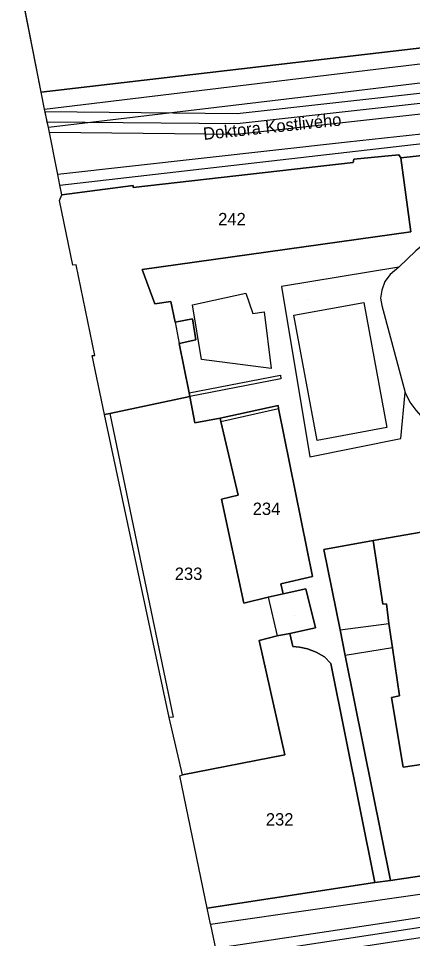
# Model space of a CAD drawing. Extents: x -263423 to -261326, y -1240067 to -1237864.
# Drawn here: x -263383 to -263319.3, y -1239723.2 to -1239574.4 of the extents above; entities that cross this region are included whole.
import ezdxf

# ---------------------------------------------------------------- set-up
doc = ezdxf.new("R2010")
doc.units = 0
for name, color, linetype in [('body_kn', 7, 'Continuous'), ('katuz_linie', 7, 'Continuous'), ('kladpar_druhypozemkov', 7, 'Continuous'), ('kladpar_hranice', 7, 'Continuous'), ('kladpar_parcelnecisla', 7, 'Continuous'), ('kladpar_plochy', 7, 'Continuous'), ('linie', 7, 'Continuous'), ('popisy', 7, 'Continuous'), ('tarchy_linie', 7, 'Continuous'), ('zappar_hrandruhpozemk', 7, 'Continuous'), ('zuob_linie', 7, 'Continuous'), ('zuob_plochy', 7, 'Continuous')]:
    doc.layers.add(name, color=color, linetype=linetype)

msp = doc.modelspace()

# ---------------------------------------------------------------- linework, layer by layer
at = {"layer": 'body_kn'}
for p, q in [((-263328.37, -1239583), (-263328.37, -1239583)), ((-263379.33, -1239586.34), (-263379.33, -1239586.34)), ((-263328.37, -1239586.11), (-263328.37, -1239586.11)), ((-263378.78, -1239589.07), (-263378.78, -1239589.07)), ((-263378.78, -1239589.07), (-263378.78, -1239589.07)), ((-263378.7, -1239589.47), (-263378.7, -1239589.47)), ((-263347.65, -1239589.78), (-263347.65, -1239589.78)), ((-263378.35, -1239591.18), (-263378.35, -1239591.18)), ((-263378.18, -1239592.03), (-263378.18, -1239592.03)), ((-263378.01, -1239592.88), (-263378.01, -1239592.88)), ((-263347.67, -1239591.48), (-263347.67, -1239591.48)), ((-263347.69, -1239593.18), (-263347.69, -1239593.18)), ((-263329.82, -1239594.43), (-263329.82, -1239594.43)), ((-263328.8, -1239597.16), (-263328.8, -1239597.16)), ((-263321.5, -1239596.46), (-263321.5, -1239596.46)), ((-263321.19, -1239596.97), (-263321.19, -1239596.97)), ((-263328.93, -1239597.73), (-263328.93, -1239597.73)), ((-263328.93, -1239597.73), (-263328.93, -1239597.73)), ((-263376.65, -1239599.64), (-263376.65, -1239599.64)), ((-263376.64, -1239599.67), (-263376.64, -1239599.67)), ((-263376.3, -1239601.35), (-263376.3, -1239601.35)), ((-263376.3, -1239601.35), (-263376.3, -1239601.35)), ((-263364.49, -1239601.44), (-263364.49, -1239601.44)), ((-263364.46, -1239601.76), (-263364.46, -1239601.76)), ((-263375.99, -1239602.91), (-263375.99, -1239602.91)), ((-263376.39, -1239603.84), (-263376.39, -1239603.84)), ((-263319.59, -1239608.9), (-263319.59, -1239608.9)), ((-263374.23, -1239614.31), (-263374.23, -1239614.31)), ((-263373.67, -1239614.26), (-263373.67, -1239614.26)), ((-263363.01, -1239615.03), (-263363.01, -1239615.03)), ((-263321.55, -1239614.62), (-263321.55, -1239614.62)), ((-263321.55, -1239614.62), (-263321.55, -1239614.62)), ((-263322.95, -1239615.83), (-263322.95, -1239615.83)), ((-263340.47, -1239617.74), (-263340.47, -1239617.74)), ((-263323.77, -1239616.97), (-263323.77, -1239616.97)), ((-263346.24, -1239618.83), (-263346.24, -1239618.83)), ((-263324.47, -1239619.64), (-263324.47, -1239619.64)), ((-263324.28, -1239618.37), (-263324.28, -1239618.37)), ((-263360.97, -1239620.55), (-263360.97, -1239620.55)), ((-263358.37, -1239620.17), (-263358.37, -1239620.17)), ((-263354.88, -1239620.74), (-263354.88, -1239620.74)), ((-263354.88, -1239620.74), (-263354.88, -1239620.74)), ((-263327.2, -1239620.34), (-263327.2, -1239620.34)), ((-263327.2, -1239620.34), (-263327.2, -1239620.34)), ((-263324.28, -1239620.84), (-263324.28, -1239620.84)), ((-263345.1, -1239622.13), (-263345.1, -1239622.13)), ((-263343.32, -1239621.87), (-263343.32, -1239621.87)), ((-263338.49, -1239622.38), (-263338.49, -1239622.38)), ((-263357.67, -1239623.53), (-263357.67, -1239623.53)), ((-263357.67, -1239623.53), (-263357.67, -1239623.53)), ((-263354.87, -1239622.96), (-263354.87, -1239622.96)), ((-263357.03, -1239626.96), (-263357.03, -1239626.96)), ((-263354.36, -1239626.39), (-263354.36, -1239626.39)), ((-263371.08, -1239628.9), (-263371.08, -1239628.9)), ((-263370.65, -1239628.9), (-263370.65, -1239628.9)), ((-263353.41, -1239629.56), (-263353.41, -1239629.56)), ((-263342.17, -1239631.02), (-263342.17, -1239631.02)), ((-263340.64, -1239632.1), (-263340.64, -1239632.1)), ((-263340.58, -1239632.67), (-263340.58, -1239632.67)), ((-263355.43, -1239634.96), (-263355.43, -1239634.96)), ((-263355.43, -1239634.96), (-263355.43, -1239634.96)), ((-263355.31, -1239635.54), (-263355.31, -1239635.54)), ((-263320.52, -1239634.88), (-263320.52, -1239634.88)), ((-263320.52, -1239634.88), (-263320.52, -1239634.88)), ((-263341.02, -1239636.99), (-263341.02, -1239636.99)), ((-263340.96, -1239637.5), (-263340.96, -1239637.5)), ((-263319.75, -1239636.47), (-263319.75, -1239636.47)), ((-263369.09, -1239638.47), (-263369.09, -1239638.47)), ((-263368.23, -1239638.29), (-263368.23, -1239638.29)), ((-263368.23, -1239638.29), (-263368.23, -1239638.29)), ((-263350.42, -1239639.03), (-263350.42, -1239639.03)), ((-263350.42, -1239639.03), (-263350.42, -1239639.03)), ((-263354.48, -1239639.79), (-263354.48, -1239639.79)), ((-263350.29, -1239639.6), (-263350.29, -1239639.6)), ((-263350.29, -1239639.6), (-263350.29, -1239639.6)), ((-263323.49, -1239640.53), (-263323.49, -1239640.53)), ((-263334.73, -1239642.64), (-263334.73, -1239642.64)), ((-263321.21, -1239642.31), (-263321.21, -1239642.31)), ((-263335.93, -1239645.3), (-263335.93, -1239645.3)), ((-263350.21, -1239652.11), (-263350.21, -1239652.11)), ((-263347.48, -1239651.47), (-263347.48, -1239651.47)), ((-263363.86, -1239659.23), (-263363.86, -1239659.23)), ((-263325.7, -1239658.83), (-263325.7, -1239658.83)), ((-263333.63, -1239660.29), (-263333.63, -1239660.29)), ((-263335.47, -1239664.62), (-263335.47, -1239664.62)), ((-263335.47, -1239664.62), (-263335.47, -1239664.62)), ((-263340.61, -1239665.83), (-263340.61, -1239665.83)), ((-263336.55, -1239666.65), (-263336.55, -1239666.65)), ((-263342.64, -1239667.99), (-263342.64, -1239667.99)), ((-263342.64, -1239667.99), (-263342.64, -1239667.99)), ((-263340.23, -1239667.41), (-263340.23, -1239667.41)), ((-263346.58, -1239668.94), (-263346.58, -1239668.94)), ((-263324.1, -1239669.12), (-263324.1, -1239669.12)), ((-263323.53, -1239669.05), (-263323.53, -1239669.05)), ((-263335.02, -1239672.94), (-263335.02, -1239672.94)), ((-263331.02, -1239673.25), (-263331.02, -1239673.25)), ((-263331.02, -1239673.25), (-263331.02, -1239673.25)), ((-263323.15, -1239672.23), (-263323.15, -1239672.23)), ((-263341.18, -1239674.21), (-263341.18, -1239674.21)), ((-263339.15, -1239673.83), (-263339.15, -1239673.83)), ((-263344.1, -1239674.98), (-263344.1, -1239674.98)), ((-263338.64, -1239675.93), (-263338.64, -1239675.93)), ((-263337.56, -1239676.05), (-263337.56, -1239676.05)), ((-263322.57, -1239676.17), (-263322.57, -1239676.17)), ((-263322.57, -1239676.17), (-263322.57, -1239676.17)), ((-263336.29, -1239676.31), (-263336.29, -1239676.31)), ((-263334.89, -1239676.88), (-263334.89, -1239676.88)), ((-263333.55, -1239677.64), (-263333.55, -1239677.64)), ((-263330.19, -1239677.38), (-263330.19, -1239677.38)), ((-263332.54, -1239678.72), (-263332.54, -1239678.72)), ((-263322.69, -1239684.17), (-263322.69, -1239684.17)), ((-263321.42, -1239683.92), (-263321.42, -1239683.92)), ((-263358.66, -1239687.42), (-263358.66, -1239687.42)), ((-263358.03, -1239687.36), (-263358.03, -1239687.36)), ((-263339.95, -1239693.46), (-263339.95, -1239693.46)), ((-263339.95, -1239693.46), (-263339.95, -1239693.46)), ((-263320.84, -1239695.48), (-263320.84, -1239695.48)), ((-263356.95, -1239696.85), (-263356.95, -1239696.85)), ((-263356.52, -1239696.68), (-263356.52, -1239696.68)), ((-263325.39, -1239714.1), (-263325.39, -1239714.1)), ((-263322.85, -1239713.78), (-263322.85, -1239713.78)), ((-263352.5, -1239718.27), (-263352.5, -1239718.27)), ((-263351.96, -1239720.82), (-263351.96, -1239720.82)), ((-263351.96, -1239720.82), (-263351.96, -1239720.82)), ((-263322.47, -1239720.38), (-263322.47, -1239720.38)), ((-263351.94, -1239720.93), (-263351.94, -1239720.93)), ((-263322.22, -1239722), (-263322.22, -1239722))]:
    msp.add_line(p, q, dxfattribs=at)
at = {"layer": 'katuz_linie'}
msp.add_lwpolyline([(-263349.43, -1239732.71), (-263351.94, -1239720.93), (-263351.96, -1239720.82), (-263352.5, -1239718.27), (-263356.95, -1239696.85), (-263356.52, -1239696.68), (-263358.66, -1239687.42), (-263369.09, -1239638.47), (-263371.08, -1239628.9), (-263370.65, -1239628.9), (-263373.67, -1239614.26), (-263374.23, -1239614.31), (-263376.39, -1239603.84), (-263375.99, -1239602.91), (-263376.3, -1239601.35), (-263376.64, -1239599.67), (-263376.65, -1239599.64), (-263378.18, -1239592.03), (-263378.78, -1239589.07), (-263379.33, -1239586.34), (-263383.02, -1239567.53)], dxfattribs=at)
at = {"layer": 'kladpar_druhypozemkov'}
for p, q in [((-263348.1, -1239605.45), (-263348.1, -1239605.45)), ((-263336.1, -1239619.91), (-263336.1, -1239619.91)), ((-263342.7, -1239652.51), (-263342.7, -1239652.51)), ((-263355.05, -1239662.59), (-263355.05, -1239662.59)), ((-263338.4, -1239671.01), (-263338.4, -1239671.01)), ((-263340.7, -1239702.21), (-263340.7, -1239702.21))]:
    msp.add_line(p, q, dxfattribs=at)
at = {"layer": 'kladpar_hranice'}
for points in [[(-263287.38, -1239574.28), (-263287.88, -1239575.74), (-263299.62, -1239577.08), (-263300.26, -1239577.14), (-263379.33, -1239586.34), (-263383.02, -1239567.53)], [(-263309.83, -1239595.69), (-263321.19, -1239596.97), (-263321.5, -1239596.46), (-263328.8, -1239597.16), (-263328.93, -1239597.73), (-263364.46, -1239601.76), (-263364.49, -1239601.44), (-263375.99, -1239602.91), (-263376.3, -1239601.35), (-263376.64, -1239599.67), (-263376.65, -1239599.64), (-263378.18, -1239592.03), (-263378.78, -1239589.07), (-263379.33, -1239586.34), (-263300.26, -1239577.14)], [(-263317.89, -1239657.49), (-263325.7, -1239658.83), (-263333.63, -1239660.29), (-263331.02, -1239673.25), (-263330.19, -1239677.38), (-263322.85, -1239713.78), (-263325.39, -1239714.1), (-263332.54, -1239678.72), (-263333.55, -1239677.64), (-263334.89, -1239676.88), (-263336.29, -1239676.31), (-263337.56, -1239676.05), (-263338.64, -1239675.93), (-263339.15, -1239673.83), (-263335.02, -1239672.94), (-263336.55, -1239666.65), (-263340.23, -1239667.41), (-263340.61, -1239665.83), (-263335.47, -1239664.62), (-263340.96, -1239637.5), (-263341.02, -1239636.99), (-263350.42, -1239639.03), (-263354.48, -1239639.79), (-263355.31, -1239635.54), (-263355.43, -1239634.96), (-263357.03, -1239626.96), (-263354.36, -1239626.39), (-263354.87, -1239622.96), (-263357.67, -1239623.53), (-263358.37, -1239620.17), (-263360.97, -1239620.55), (-263363.01, -1239615.03), (-263319.59, -1239608.9), (-263321.19, -1239596.97), (-263309.83, -1239595.69)], [(-263328.93, -1239597.73), (-263328.8, -1239597.16), (-263321.5, -1239596.46), (-263321.19, -1239596.97), (-263319.59, -1239608.9), (-263363.01, -1239615.03), (-263360.97, -1239620.55), (-263358.37, -1239620.17), (-263357.67, -1239623.53), (-263354.87, -1239622.96), (-263354.36, -1239626.39), (-263357.03, -1239626.96), (-263355.43, -1239634.96), (-263355.31, -1239635.54), (-263368.23, -1239638.29), (-263369.09, -1239638.47), (-263371.08, -1239628.9), (-263370.65, -1239628.9), (-263373.67, -1239614.26), (-263374.23, -1239614.31), (-263376.39, -1239603.84), (-263375.99, -1239602.91), (-263364.49, -1239601.44), (-263364.46, -1239601.76), (-263328.93, -1239597.73)], [(-263350.42, -1239639.03), (-263350.29, -1239639.6), (-263347.48, -1239651.47), (-263350.21, -1239652.11), (-263346.58, -1239668.94), (-263342.64, -1239667.99), (-263340.23, -1239667.41), (-263336.55, -1239666.65), (-263335.02, -1239672.94), (-263339.15, -1239673.83), (-263341.18, -1239674.21), (-263344.1, -1239674.98), (-263339.95, -1239693.46), (-263356.52, -1239696.68), (-263358.66, -1239687.42), (-263369.09, -1239638.47), (-263368.23, -1239638.29), (-263355.31, -1239635.54), (-263354.48, -1239639.79), (-263350.42, -1239639.03)], [(-263335.47, -1239664.62), (-263340.61, -1239665.83), (-263340.23, -1239667.41), (-263342.64, -1239667.99), (-263346.58, -1239668.94), (-263350.21, -1239652.11), (-263347.48, -1239651.47), (-263350.29, -1239639.6), (-263350.42, -1239639.03), (-263341.02, -1239636.99), (-263340.96, -1239637.5), (-263335.47, -1239664.62)], [(-263312.4, -1239694.21), (-263320.84, -1239695.48), (-263322.69, -1239684.17), (-263321.42, -1239683.92), (-263322.57, -1239676.17), (-263323.15, -1239672.23), (-263323.53, -1239669.05), (-263324.1, -1239669.12), (-263325.7, -1239658.83), (-263317.89, -1239657.49)], [(-263310.98, -1239712), (-263322.85, -1239713.78), (-263330.19, -1239677.38), (-263331.02, -1239673.25), (-263333.63, -1239660.29), (-263325.7, -1239658.83), (-263324.1, -1239669.12), (-263323.53, -1239669.05), (-263323.15, -1239672.23), (-263322.57, -1239676.17), (-263321.42, -1239683.92), (-263322.69, -1239684.17), (-263320.84, -1239695.48), (-263312.4, -1239694.21)], [(-263339.95, -1239693.46), (-263344.1, -1239674.98), (-263341.18, -1239674.21), (-263339.15, -1239673.83), (-263338.64, -1239675.93), (-263337.56, -1239676.05), (-263336.29, -1239676.31), (-263334.89, -1239676.88), (-263333.55, -1239677.64), (-263332.54, -1239678.72), (-263325.39, -1239714.1), (-263352.5, -1239718.27), (-263356.95, -1239696.85), (-263356.52, -1239696.68), (-263339.95, -1239693.46)], [(-263349.43, -1239732.71), (-263351.94, -1239720.93), (-263351.96, -1239720.82), (-263352.5, -1239718.27), (-263325.39, -1239714.1), (-263322.85, -1239713.78), (-263310.98, -1239712), (-263266.99, -1239705.68)]]:
    msp.add_lwpolyline(points, dxfattribs=at)
at = {"layer": 'kladpar_plochy'}
for p, q in [((-263379.33, -1239586.34), (-263383.02, -1239567.53)), ((-263300.26, -1239577.14), (-263379.33, -1239586.34)), ((-263321.19, -1239596.97), (-263309.83, -1239595.69)), ((-263319.59, -1239608.9), (-263321.19, -1239596.97)), ((-263363.01, -1239615.03), (-263319.59, -1239608.9)), ((-263360.97, -1239620.55), (-263363.01, -1239615.03)), ((-263358.37, -1239620.17), (-263360.97, -1239620.55)), ((-263357.67, -1239623.53), (-263358.37, -1239620.17)), ((-263354.87, -1239622.96), (-263357.67, -1239623.53)), ((-263354.36, -1239626.39), (-263354.87, -1239622.96)), ((-263357.03, -1239626.96), (-263354.36, -1239626.39)), ((-263355.43, -1239634.96), (-263357.03, -1239626.96)), ((-263355.31, -1239635.54), (-263355.43, -1239634.96)), ((-263354.48, -1239639.79), (-263355.31, -1239635.54)), ((-263341.02, -1239636.99), (-263350.42, -1239639.03)), ((-263340.96, -1239637.5), (-263341.02, -1239636.99)), ((-263335.47, -1239664.62), (-263340.96, -1239637.5)), ((-263350.42, -1239639.03), (-263354.48, -1239639.79)), ((-263317.89, -1239657.49), (-263325.7, -1239658.83)), ((-263325.7, -1239658.83), (-263333.63, -1239660.29)), ((-263333.63, -1239660.29), (-263331.02, -1239673.25)), ((-263340.61, -1239665.83), (-263335.47, -1239664.62)), ((-263340.23, -1239667.41), (-263340.61, -1239665.83)), ((-263336.55, -1239666.65), (-263340.23, -1239667.41)), ((-263335.02, -1239672.94), (-263336.55, -1239666.65)), ((-263339.15, -1239673.83), (-263335.02, -1239672.94)), ((-263331.02, -1239673.25), (-263330.19, -1239677.38)), ((-263338.64, -1239675.93), (-263339.15, -1239673.83)), ((-263337.56, -1239676.05), (-263338.64, -1239675.93)), ((-263336.29, -1239676.31), (-263337.56, -1239676.05)), ((-263334.89, -1239676.88), (-263336.29, -1239676.31)), ((-263333.55, -1239677.64), (-263334.89, -1239676.88)), ((-263332.54, -1239678.72), (-263333.55, -1239677.64)), ((-263330.19, -1239677.38), (-263322.85, -1239713.78)), ((-263325.39, -1239714.1), (-263332.54, -1239678.72)), ((-263322.85, -1239713.78), (-263325.39, -1239714.1))]:
    msp.add_line(p, q, dxfattribs=at)
for points in [[(-263309.83, -1239595.69), (-263321.19, -1239596.97), (-263321.5, -1239596.46), (-263328.8, -1239597.16), (-263328.93, -1239597.73), (-263364.46, -1239601.76), (-263364.49, -1239601.44), (-263375.99, -1239602.91), (-263376.3, -1239601.35), (-263376.64, -1239599.67), (-263376.65, -1239599.64), (-263378.18, -1239592.03), (-263378.78, -1239589.07), (-263379.33, -1239586.34), (-263300.26, -1239577.14)], [(-263312.4, -1239694.21), (-263320.84, -1239695.48), (-263322.69, -1239684.17), (-263321.42, -1239683.92), (-263322.57, -1239676.17), (-263323.15, -1239672.23), (-263323.53, -1239669.05), (-263324.1, -1239669.12), (-263325.7, -1239658.83), (-263317.89, -1239657.49)], [(-263310.98, -1239712), (-263322.85, -1239713.78), (-263330.19, -1239677.38), (-263331.02, -1239673.25), (-263333.63, -1239660.29), (-263325.7, -1239658.83), (-263324.1, -1239669.12), (-263323.53, -1239669.05), (-263323.15, -1239672.23), (-263322.57, -1239676.17), (-263321.42, -1239683.92), (-263322.69, -1239684.17), (-263320.84, -1239695.48), (-263312.4, -1239694.21)], [(-263349.43, -1239732.71), (-263351.94, -1239720.93), (-263351.96, -1239720.82), (-263352.5, -1239718.27), (-263325.39, -1239714.1), (-263322.85, -1239713.78), (-263310.98, -1239712), (-263266.99, -1239705.68), (-263251.05, -1239703.32), (-263242.87, -1239702.17), (-263223.13, -1239699.36)]]:
    msp.add_lwpolyline(points, dxfattribs=at)
for points in [[(-263328.93, -1239597.73), (-263328.8, -1239597.16), (-263321.5, -1239596.46), (-263321.19, -1239596.97), (-263319.59, -1239608.9), (-263363.01, -1239615.03), (-263360.97, -1239620.55), (-263358.37, -1239620.17), (-263357.67, -1239623.53), (-263354.87, -1239622.96), (-263354.36, -1239626.39), (-263357.03, -1239626.96), (-263355.43, -1239634.96), (-263355.31, -1239635.54), (-263368.23, -1239638.29), (-263369.09, -1239638.47), (-263371.08, -1239628.9), (-263370.65, -1239628.9), (-263373.67, -1239614.26), (-263374.23, -1239614.31), (-263376.39, -1239603.84), (-263375.99, -1239602.91), (-263364.49, -1239601.44), (-263364.46, -1239601.76)], [(-263350.42, -1239639.03), (-263350.29, -1239639.6), (-263347.48, -1239651.47), (-263350.21, -1239652.11), (-263346.58, -1239668.94), (-263342.64, -1239667.99), (-263340.23, -1239667.41), (-263336.55, -1239666.65), (-263335.02, -1239672.94), (-263339.15, -1239673.83), (-263341.18, -1239674.21), (-263344.1, -1239674.98), (-263339.95, -1239693.46), (-263356.52, -1239696.68), (-263358.66, -1239687.42), (-263369.09, -1239638.47), (-263368.23, -1239638.29), (-263355.31, -1239635.54), (-263354.48, -1239639.79)], [(-263335.47, -1239664.62), (-263340.61, -1239665.83), (-263340.23, -1239667.41), (-263342.64, -1239667.99), (-263346.58, -1239668.94), (-263350.21, -1239652.11), (-263347.48, -1239651.47), (-263350.29, -1239639.6), (-263350.42, -1239639.03), (-263341.02, -1239636.99), (-263340.96, -1239637.5)], [(-263339.95, -1239693.46), (-263344.1, -1239674.98), (-263341.18, -1239674.21), (-263339.15, -1239673.83), (-263338.64, -1239675.93), (-263337.56, -1239676.05), (-263336.29, -1239676.31), (-263334.89, -1239676.88), (-263333.55, -1239677.64), (-263332.54, -1239678.72), (-263325.39, -1239714.1), (-263352.5, -1239718.27), (-263356.95, -1239696.85), (-263356.52, -1239696.68)]]:
    msp.add_lwpolyline(points, close=True, dxfattribs=at)
at = {"layer": 'linie'}
msp.add_lwpolyline([(-263349.43, -1239732.71), (-263351.94, -1239720.93), (-263351.96, -1239720.82), (-263352.5, -1239718.27), (-263356.95, -1239696.85), (-263356.52, -1239696.68), (-263358.66, -1239687.42), (-263369.09, -1239638.47), (-263371.08, -1239628.9), (-263370.65, -1239628.9), (-263373.67, -1239614.26), (-263374.23, -1239614.31), (-263376.39, -1239603.84), (-263375.99, -1239602.91), (-263376.3, -1239601.35), (-263376.64, -1239599.67), (-263376.65, -1239599.64), (-263378.18, -1239592.03), (-263378.78, -1239589.07), (-263379.33, -1239586.34), (-263383.02, -1239567.53)], dxfattribs=at)
at = {"layer": 'tarchy_linie'}
for points in [[(-263201.24, -1239576.77), (-263248.04, -1239582.1), (-263297.99, -1239587.66), (-263347.69, -1239593.18), (-263378.01, -1239592.88), (-263378.18, -1239592.03), (-263378.35, -1239591.18), (-263378.7, -1239589.47), (-263347.65, -1239589.78), (-263298.37, -1239584.28), (-263248.42, -1239578.72), (-263201.54, -1239573.39)], [(-263198.58, -1239574.76), (-263248.23, -1239580.41), (-263298.18, -1239585.97), (-263347.67, -1239591.48), (-263378.35, -1239591.18)], [(-263229.84, -1239709.68), (-263275.95, -1239716.62), (-263321.97, -1239723.64), (-263350.44, -1239727.98), (-263350.78, -1239726.36), (-263351.13, -1239724.74), (-263322.47, -1239720.38), (-263276.45, -1239713.36), (-263230.88, -1239706.5), (-263188.22, -1239700.5)], [(-263185.2, -1239701.74), (-263230.36, -1239708.08), (-263276.2, -1239715), (-263322.22, -1239722), (-263350.78, -1239726.36)]]:
    msp.add_lwpolyline(points, dxfattribs=at)
at = {"layer": 'zappar_hrandruhpozemk'}
for p, q in [((-263328.37, -1239583), (-263278.55, -1239577)), ((-263278.8, -1239580.11), (-263328.37, -1239586.11)), ((-263378.78, -1239589.07), (-263328.37, -1239583)), ((-263328.37, -1239586.11), (-263378.18, -1239592.03)), ((-263278.41, -1239588.75), (-263329.82, -1239594.43)), ((-263376.3, -1239601.35), (-263310.27, -1239593.78)), ((-263329.82, -1239594.43), (-263376.64, -1239599.67)), ((-263321.55, -1239614.62), (-263340.47, -1239617.74)), ((-263354.88, -1239620.74), (-263346.24, -1239618.83)), ((-263324.28, -1239620.84), (-263320.52, -1239634.88)), ((-263357.67, -1239623.53), (-263357.03, -1239626.96)), ((-263340.58, -1239632.67), (-263355.31, -1239635.54)), ((-263350.29, -1239639.6), (-263340.96, -1239637.5)), ((-263368.23, -1239638.29), (-263363.86, -1239659.23)), ((-263363.86, -1239659.23), (-263358.03, -1239687.36)), ((-263342.64, -1239667.99), (-263341.18, -1239674.21)), ((-263331.02, -1239673.25), (-263323.15, -1239672.23)), ((-263322.57, -1239676.17), (-263330.19, -1239677.38)), ((-263358.03, -1239687.36), (-263358.66, -1239687.42)), ((-263351.96, -1239720.82), (-263312.18, -1239715.11))]:
    msp.add_line(p, q, dxfattribs=at)
for points in [[(-263309.83, -1239595.69), (-263309.44, -1239596.89), (-263309.12, -1239598.35), (-263309.12, -1239599.82), (-263309.38, -1239601.4), (-263309.82, -1239603.05), (-263310.58, -1239604.52), (-263311.53, -1239605.98), (-263312.99, -1239607.31), (-263315.59, -1239609.34), (-263318.76, -1239612.01), (-263321.55, -1239614.62), (-263322.95, -1239615.83), (-263323.77, -1239616.97), (-263324.28, -1239618.37), (-263324.47, -1239619.64), (-263324.28, -1239620.84)], [(-263340.47, -1239617.74), (-263335.93, -1239645.3), (-263321.21, -1239642.31), (-263320.52, -1239634.88)], [(-263346.24, -1239618.83), (-263345.1, -1239622.13), (-263343.32, -1239621.87), (-263342.17, -1239631.02), (-263353.41, -1239629.56), (-263354.88, -1239620.74)], [(-263327.2, -1239620.34), (-263323.49, -1239640.53), (-263334.73, -1239642.64), (-263338.49, -1239622.38), (-263327.2, -1239620.34)], [(-263355.43, -1239634.96), (-263340.64, -1239632.1), (-263340.58, -1239632.67)], [(-263320.52, -1239634.88), (-263319.75, -1239636.47), (-263318.8, -1239637.74), (-263317.59, -1239639.07), (-263316.45, -1239640.08), (-263315.24, -1239640.85), (-263313.72, -1239641.48), (-263311.94, -1239641.8), (-263310.22, -1239641.67), (-263306.73, -1239641.22), (-263300.2, -1239640.27), (-263296.01, -1239639.69)]]:
    msp.add_lwpolyline(points, dxfattribs=at)
at = {"layer": 'zuob_linie'}
msp.add_lwpolyline([(-263349.43, -1239732.71), (-263351.94, -1239720.93), (-263351.96, -1239720.82), (-263352.5, -1239718.27), (-263356.95, -1239696.85), (-263356.52, -1239696.68), (-263358.66, -1239687.42), (-263369.09, -1239638.47), (-263371.08, -1239628.9), (-263370.65, -1239628.9), (-263373.67, -1239614.26), (-263374.23, -1239614.31), (-263376.39, -1239603.84), (-263375.99, -1239602.91), (-263376.3, -1239601.35), (-263376.64, -1239599.67), (-263376.65, -1239599.64), (-263378.18, -1239592.03), (-263378.78, -1239589.07), (-263379.33, -1239586.34), (-263383.02, -1239567.53)], dxfattribs=at)
at = {"layer": 'zuob_plochy'}
msp.add_lwpolyline([(-263349.43, -1239732.71), (-263351.94, -1239720.93), (-263351.96, -1239720.82), (-263352.5, -1239718.27), (-263356.95, -1239696.85), (-263356.52, -1239696.68), (-263358.66, -1239687.42), (-263369.09, -1239638.47), (-263371.08, -1239628.9), (-263370.65, -1239628.9), (-263373.67, -1239614.26), (-263374.23, -1239614.31), (-263376.39, -1239603.84), (-263375.99, -1239602.91), (-263376.3, -1239601.35), (-263376.64, -1239599.67), (-263376.65, -1239599.64), (-263378.18, -1239592.03), (-263378.78, -1239589.07), (-263379.33, -1239586.34), (-263383.02, -1239567.53)], dxfattribs=at)

# ---------------------------------------------------------------- texts
at = {"layer": 'kladpar_parcelnecisla'}
for s, p in [('242', (-263350.73, -1239607.86)), ('234', (-263345.14, -1239654.69)), ('233', (-263357.74, -1239665.19)), ('232', (-263343.02, -1239704.89))]:
    msp.add_text(s, height=2, dxfattribs=at).set_placement(p)
at = {"layer": 'popisy'}
msp.add_text('Doktora Kostlivého', height=2, rotation=6, dxfattribs=at).set_placement((-263353.05, -1239594.07))

doc.saveas('drawing.dxf')
